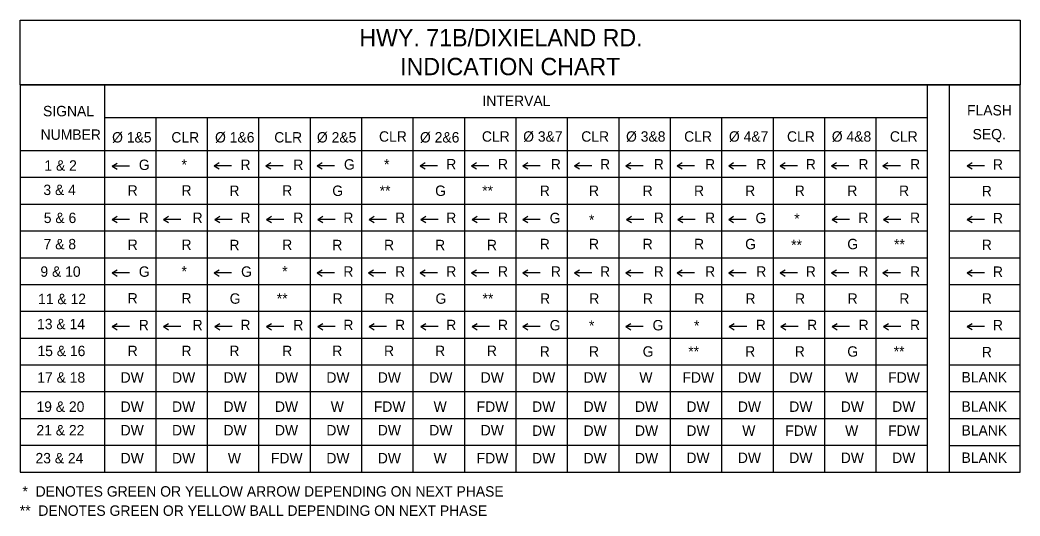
# Model space of a CAD drawing. Extents: x -19.5 to 29.5, y 0.4 to 10.6.
# Drawn here: x -12.11 to -4.42, y 0.78 to 4.6 of the extents above; entities that cross this region are included whole.
import ezdxf

# ---------------------------------------------------------------- set-up
doc = ezdxf.new("R2010")
doc.units = 0
for name, color, linetype in [('$', 7, 'Continuous'), ('PHASE', 7, 'Continuous'), ('TBLBDR', 7, 'Continuous'), ('TBLLINE', 7, 'Continuous'), ('TBLTEXT', 7, 'Continuous'), ('TITEXT', 7, 'Continuous')]:
    doc.layers.add(name, color=color, linetype=linetype)

msp = doc.modelspace()

# ---------------------------------------------------------------- linework, layer by layer
at = {"layer": 'PHASE'}
for p, q in [((-11.4033, 3.4746), (-11.3649, 3.4989)), ((-11.4033, 3.4746), (-11.3649, 3.4503)), ((-11.2697, 3.4746), (-11.4033, 3.4746)), ((-10.6165, 3.4775), (-10.5781, 3.5018)), ((-10.6165, 3.4775), (-10.5781, 3.4532)), ((-10.4829, 3.4775), (-10.6165, 3.4775)), ((-10.2207, 3.4775), (-10.1822, 3.5018)), ((-10.2207, 3.4775), (-10.1822, 3.4532)), ((-10.0871, 3.4775), (-10.2207, 3.4775)), ((-9.8249, 3.4775), (-9.7864, 3.5018)), ((-9.8249, 3.4775), (-9.7864, 3.4532)), ((-9.6912, 3.4775), (-9.8249, 3.4775)), ((-9.0332, 3.4783), (-8.9947, 3.5026)), ((-9.0332, 3.4783), (-8.9947, 3.454)), ((-8.8996, 3.4783), (-9.0332, 3.4783)), ((-8.6373, 3.4783), (-8.5989, 3.5026)), ((-8.6373, 3.4783), (-8.5989, 3.454)), ((-8.5037, 3.4783), (-8.6373, 3.4783)), ((-8.2415, 3.4783), (-8.203, 3.5026)), ((-8.2415, 3.4783), (-8.203, 3.454)), ((-8.1079, 3.4783), (-8.2415, 3.4783)), ((-7.8457, 3.4783), (-7.8072, 3.5026)), ((-7.8457, 3.4783), (-7.8072, 3.454)), ((-7.712, 3.4783), (-7.8457, 3.4783)), ((-7.4498, 3.4783), (-7.4114, 3.5026)), ((-7.4498, 3.4783), (-7.4114, 3.454)), ((-7.3162, 3.4783), (-7.4498, 3.4783)), ((-7.054, 3.4783), (-7.0155, 3.5026)), ((-7.054, 3.4783), (-7.0155, 3.454)), ((-6.9204, 3.4783), (-7.054, 3.4783)), ((-6.6581, 3.4783), (-6.6197, 3.5026)), ((-6.6581, 3.4783), (-6.6197, 3.454)), ((-6.5245, 3.4783), (-6.6581, 3.4783)), ((-6.2623, 3.4783), (-6.2238, 3.5026)), ((-6.2623, 3.4783), (-6.2238, 3.454)), ((-6.1287, 3.4783), (-6.2623, 3.4783)), ((-5.8665, 3.4783), (-5.828, 3.5026)), ((-5.8665, 3.4783), (-5.828, 3.454)), ((-5.7328, 3.4783), (-5.8665, 3.4783)), ((-5.4706, 3.4783), (-5.4322, 3.5026)), ((-5.4706, 3.4783), (-5.4322, 3.454)), ((-5.337, 3.4783), (-5.4706, 3.4783)), ((-4.8224, 3.4775), (-4.7839, 3.5018)), ((-4.8224, 3.4775), (-4.7839, 3.4532)), ((-4.6888, 3.4775), (-4.8224, 3.4775)), ((-11.4033, 3.0652), (-11.3649, 3.0895)), ((-11.0075, 3.0652), (-10.969, 3.0895)), ((-10.6117, 3.0652), (-10.5732, 3.0895)), ((-10.2158, 3.0652), (-10.1773, 3.0895)), ((-9.82, 3.0652), (-9.7815, 3.0895)), ((-9.4241, 3.0652), (-9.3857, 3.0895)), ((-9.0283, 3.0652), (-8.9898, 3.0895)), ((-8.6325, 3.0652), (-8.594, 3.0895)), ((-8.2415, 3.0652), (-8.203, 3.0895)), ((-7.4449, 3.0652), (-7.4065, 3.0895)), ((-7.0491, 3.0652), (-7.0106, 3.0895)), ((-6.6581, 3.0652), (-6.6197, 3.0895)), ((-5.8616, 3.0652), (-5.8231, 3.0895)), ((-5.4657, 3.0652), (-5.4273, 3.0895)), ((-4.8224, 3.0648), (-4.7839, 3.0891)), ((-11.4033, 3.0652), (-11.3649, 3.0409)), ((-11.2697, 3.0652), (-11.4033, 3.0652)), ((-11.0075, 3.0652), (-10.969, 3.0409)), ((-10.8739, 3.0652), (-11.0075, 3.0652)), ((-10.6117, 3.0652), (-10.5732, 3.0409)), ((-10.478, 3.0652), (-10.6117, 3.0652)), ((-10.2158, 3.0652), (-10.1773, 3.0409)), ((-10.0822, 3.0652), (-10.2158, 3.0652)), ((-9.82, 3.0652), (-9.7815, 3.0409)), ((-9.6864, 3.0652), (-9.82, 3.0652)), ((-9.4241, 3.0652), (-9.3857, 3.0409)), ((-9.2905, 3.0652), (-9.4241, 3.0652)), ((-9.0283, 3.0652), (-8.9898, 3.0409)), ((-8.8947, 3.0652), (-9.0283, 3.0652)), ((-8.6325, 3.0652), (-8.594, 3.0409)), ((-8.4988, 3.0652), (-8.6325, 3.0652)), ((-8.2415, 3.0652), (-8.203, 3.0409)), ((-8.1079, 3.0652), (-8.2415, 3.0652)), ((-7.4449, 3.0652), (-7.4065, 3.0409)), ((-7.3113, 3.0652), (-7.4449, 3.0652)), ((-7.0491, 3.0652), (-7.0106, 3.0409)), ((-6.9155, 3.0652), (-7.0491, 3.0652)), ((-6.6581, 3.0652), (-6.6197, 3.0409)), ((-6.5245, 3.0652), (-6.6581, 3.0652)), ((-5.8616, 3.0652), (-5.8231, 3.0409)), ((-5.728, 3.0652), (-5.8616, 3.0652)), ((-5.4657, 3.0652), (-5.4273, 3.0409)), ((-5.3321, 3.0652), (-5.4657, 3.0652)), ((-4.8224, 3.0648), (-4.7839, 3.0406)), ((-4.6888, 3.0648), (-4.8224, 3.0648)), ((-11.4033, 2.6529), (-11.3649, 2.6772)), ((-11.4033, 2.6529), (-11.3649, 2.6287)), ((-11.2697, 2.6529), (-11.4033, 2.6529)), ((-10.6165, 2.6529), (-10.5781, 2.6772)), ((-10.6165, 2.6529), (-10.5781, 2.6287)), ((-10.4829, 2.6529), (-10.6165, 2.6529)), ((-9.8249, 2.6529), (-9.7864, 2.6772)), ((-9.8249, 2.6529), (-9.7864, 2.6287)), ((-9.6912, 2.6529), (-9.8249, 2.6529)), ((-9.429, 2.6529), (-9.3905, 2.6772)), ((-9.429, 2.6529), (-9.3905, 2.6287)), ((-9.2954, 2.6529), (-9.429, 2.6529)), ((-9.0332, 2.6529), (-8.9947, 2.6772)), ((-9.0332, 2.6529), (-8.9947, 2.6287)), ((-8.8996, 2.6529), (-9.0332, 2.6529)), ((-8.6373, 2.6529), (-8.5989, 2.6772)), ((-8.6373, 2.6529), (-8.5989, 2.6287)), ((-8.5037, 2.6529), (-8.6373, 2.6529)), ((-8.2415, 2.6529), (-8.203, 2.6772)), ((-8.2415, 2.6529), (-8.203, 2.6287)), ((-8.1079, 2.6529), (-8.2415, 2.6529)), ((-7.8457, 2.6529), (-7.8072, 2.6772)), ((-7.8457, 2.6529), (-7.8072, 2.6287)), ((-7.712, 2.6529), (-7.8457, 2.6529)), ((-7.4498, 2.6529), (-7.4114, 2.6772)), ((-7.4498, 2.6529), (-7.4114, 2.6287)), ((-7.3162, 2.6529), (-7.4498, 2.6529)), ((-7.054, 2.6529), (-7.0155, 2.6772)), ((-7.054, 2.6529), (-7.0155, 2.6287)), ((-6.9204, 2.6529), (-7.054, 2.6529)), ((-6.6581, 2.6529), (-6.6197, 2.6772)), ((-6.6581, 2.6529), (-6.6197, 2.6287)), ((-6.5245, 2.6529), (-6.6581, 2.6529)), ((-6.2623, 2.6529), (-6.2238, 2.6772)), ((-6.2623, 2.6529), (-6.2238, 2.6287)), ((-6.1287, 2.6529), (-6.2623, 2.6529)), ((-5.8665, 2.6529), (-5.828, 2.6772)), ((-5.8665, 2.6529), (-5.828, 2.6287)), ((-5.7328, 2.6529), (-5.8665, 2.6529)), ((-5.4706, 2.6529), (-5.4322, 2.6772)), ((-5.4706, 2.6529), (-5.4322, 2.6287)), ((-5.337, 2.6529), (-5.4706, 2.6529)), ((-4.8224, 2.6529), (-4.7839, 2.6772)), ((-4.8224, 2.6529), (-4.7839, 2.6287)), ((-4.6888, 2.6529), (-4.8224, 2.6529)), ((-11.4033, 2.2407), (-11.3649, 2.2649)), ((-11.4033, 2.2407), (-11.3649, 2.2164)), ((-11.2697, 2.2407), (-11.4033, 2.2407)), ((-11.0075, 2.2407), (-10.969, 2.2649)), ((-11.0075, 2.2407), (-10.969, 2.2164)), ((-10.8739, 2.2407), (-11.0075, 2.2407)), ((-10.6117, 2.2407), (-10.5732, 2.2649)), ((-10.6117, 2.2407), (-10.5732, 2.2164)), ((-10.478, 2.2407), (-10.6117, 2.2407)), ((-10.2158, 2.2407), (-10.1773, 2.2649)), ((-10.2158, 2.2407), (-10.1773, 2.2164)), ((-10.0822, 2.2407), (-10.2158, 2.2407)), ((-9.82, 2.2407), (-9.7815, 2.2649)), ((-9.82, 2.2407), (-9.7815, 2.2164)), ((-9.6864, 2.2407), (-9.82, 2.2407)), ((-9.4241, 2.2407), (-9.3857, 2.2649)), ((-9.4241, 2.2407), (-9.3857, 2.2164)), ((-9.2905, 2.2407), (-9.4241, 2.2407)), ((-9.0283, 2.2407), (-8.9898, 2.2649)), ((-9.0283, 2.2407), (-8.9898, 2.2164)), ((-8.8947, 2.2407), (-9.0283, 2.2407)), ((-8.6325, 2.2407), (-8.594, 2.2649)), ((-8.6325, 2.2407), (-8.594, 2.2164)), ((-8.4988, 2.2407), (-8.6325, 2.2407)), ((-8.2415, 2.2407), (-8.203, 2.2649)), ((-8.2415, 2.2407), (-8.203, 2.2164)), ((-8.1079, 2.2407), (-8.2415, 2.2407)), ((-7.4498, 2.2407), (-7.4114, 2.2649)), ((-7.4498, 2.2407), (-7.4114, 2.2164)), ((-7.3162, 2.2407), (-7.4498, 2.2407)), ((-6.6533, 2.2407), (-6.6148, 2.2649)), ((-6.6533, 2.2407), (-6.6148, 2.2164)), ((-6.5196, 2.2407), (-6.6533, 2.2407)), ((-6.2574, 2.2407), (-6.219, 2.2649)), ((-6.2574, 2.2407), (-6.219, 2.2164)), ((-6.1238, 2.2407), (-6.2574, 2.2407)), ((-5.8616, 2.2407), (-5.8231, 2.2649)), ((-5.8616, 2.2407), (-5.8231, 2.2164)), ((-5.728, 2.2407), (-5.8616, 2.2407)), ((-5.4657, 2.2407), (-5.4273, 2.2649)), ((-5.4657, 2.2407), (-5.4273, 2.2164)), ((-5.3321, 2.2407), (-5.4657, 2.2407)), ((-4.8224, 2.2411), (-4.7839, 2.2653)), ((-4.8224, 2.2411), (-4.7839, 2.2168)), ((-4.6888, 2.2411), (-4.8224, 2.2411))]:
    msp.add_line(p, q, dxfattribs=at)
at = {"layer": 'TBLBDR'}
for p, q in [((-12.1107, 4.1013), (-12.1107, 1.1214)), ((-12.1107, 4.1013), (-4.4161, 4.1013)), ((-11.4602, 1.1214), (-11.4602, 4.1013)), ((-5.1267, 1.1214), (-5.1267, 4.1013)), ((-4.9604, 4.1013), (-4.9604, 1.1214)), ((-4.4161, 1.1214), (-4.4161, 4.1013)), ((-8.2934, 1.1214), (-8.2934, 3.8486)), ((-12.1107, 3.5951), (-5.1267, 3.5951)), ((-4.9604, 3.5951), (-4.4161, 3.5951)), ((-12.1107, 1.9459), (-5.1267, 1.9459)), ((-4.9604, 1.9452), (-4.4161, 1.9452)), ((-12.1107, 1.1214), (-4.4161, 1.1214))]:
    msp.add_line(p, q, dxfattribs=at)
msp.add_lwpolyline([(-12.1107, 4.599), (-4.4161, 4.599), (-4.4161, 4.1013), (-12.1107, 4.1013)], close=True, dxfattribs=at)
at = {"layer": 'TBLLINE'}
for p, q in [((-11.4602, 3.8486), (-5.1267, 3.8486)), ((-11.0643, 1.1214), (-11.0643, 3.8486)), ((-10.6685, 1.1214), (-10.6685, 3.8486)), ((-10.2726, 1.1214), (-10.2726, 3.8486)), ((-9.8768, 1.1214), (-9.8768, 3.8486)), ((-9.481, 1.1214), (-9.481, 3.8486)), ((-9.0851, 1.1214), (-9.0851, 3.8486)), ((-8.6893, 1.1214), (-8.6893, 3.8486)), ((-7.8976, 1.1214), (-7.8976, 3.8486)), ((-7.5018, 1.1214), (-7.5018, 3.8486)), ((-7.1059, 1.1214), (-7.1059, 3.8486)), ((-6.7101, 1.1214), (-6.7101, 3.8486)), ((-6.3143, 1.1214), (-6.3143, 3.8486)), ((-5.9184, 1.1214), (-5.9184, 3.8486)), ((-5.5226, 1.1214), (-5.5226, 3.8486)), ((-12.1107, 3.3889), (-5.1267, 3.3889)), ((-4.9604, 3.3897), (-4.4161, 3.3897)), ((-12.1107, 3.1828), (-5.1267, 3.1828)), ((-4.9604, 3.1832), (-4.4161, 3.1832)), ((-12.1107, 2.9766), (-5.1267, 2.9766)), ((-4.9604, 2.9766), (-4.4161, 2.9766)), ((-12.1107, 2.7705), (-5.1267, 2.7705)), ((-4.9604, 2.7701), (-4.4161, 2.7701)), ((-12.1107, 2.5644), (-5.1267, 2.5644)), ((-4.9604, 2.5648), (-4.4161, 2.5648)), ((-12.1107, 2.3582), (-5.1267, 2.3582)), ((-4.9604, 2.3582), (-4.4161, 2.3582)), ((-12.1107, 2.1521), (-5.1267, 2.1521)), ((-4.9604, 2.1517), (-4.4161, 2.1517)), ((-12.1107, 1.7398), (-5.1267, 1.7398)), ((-4.9604, 1.7398), (-4.4161, 1.7398)), ((-12.1107, 1.5337), (-5.1267, 1.5337)), ((-4.9604, 1.5333), (-4.4161, 1.5333)), ((-12.1107, 1.3275), (-5.1267, 1.3275)), ((-4.9604, 1.3267), (-4.4161, 1.3267))]:
    msp.add_line(p, q, dxfattribs=at)

# ---------------------------------------------------------------- texts
at = {"layer": '$'}
for s, p in [('HWY. 71B/DIXIELAND RD.', (-9.5004, 4.3964)), ('INDICATION CHART', (-9.1861, 4.1744))]:
    msp.add_text(s, height=0.133334, dxfattribs=at).set_placement(p)
at = {"layer": 'TBLTEXT'}
for s, height, p in [('1 & 2', 0.08, (-11.9241, 3.4401)), ('G', 0.08, (-11.1973, 3.4451)), ('*', 0.08, (-10.8689, 3.4467)), ('R', 0.08, (-10.415, 3.4456)), ('R', 0.08, (-10.0086, 3.4451)), ('G', 0.08, (-9.6188, 3.448)), ('*', 0.08, (-9.3102, 3.4488)), ('R', 0.08, (-8.8316, 3.4497)), ('R', 0.08, (-8.4332, 3.4497)), ('R', 0.08, (-8.0263, 3.4493)), ('R', 0.08, (-7.6477, 3.4493)), ('R', 0.08, (-7.2346, 3.4493)), ('R', 0.08, (-6.8393, 3.4493)), ('R', 0.08, (-6.4457, 3.4493)), ('R', 0.08, (-6.0644, 3.4493)), ('R', 0.08, (-5.6596, 3.4493)), ('R', 0.08, (-5.2615, 3.4493)), ('R', 0.08, (-4.6245, 3.4476)), ('3 & 4', 0.08, (-11.9317, 3.2525)), ('R', 0.08, (-11.2831, 3.2475)), ('R', 0.08, (-10.8689, 3.2475)), ('R', 0.08, (-10.5003, 3.2455)), ('R', 0.08, (-10.094, 3.2475)), ('G', 0.08, (-9.7087, 3.2455)), ('**', 0.08, (-9.3439, 3.2455)), ('G', 0.08, (-8.917, 3.2455)), ('**', 0.08, (-8.5547, 3.2455)), ('R', 0.08, (-8.1116, 3.2455)), ('R', 0.08, (-7.7331, 3.2455)), ('R', 0.08, (-7.3199, 3.2455)), ('R', 0.08, (-6.9247, 3.2455)), ('R', 0.08, (-6.5311, 3.2455)), ('R', 0.08, (-6.1497, 3.2455)), ('R', 0.08, (-5.745, 3.2455)), ('R', 0.08, (-5.3469, 3.2455)), ('R', 0.08, (-4.7099, 3.2423)), ('5 & 6', 0.08, (-11.9287, 3.037)), ('R', 0.08, (-11.1977, 3.037)), ('R', 0.08, (-10.7836, 3.037)), ('R', 0.08, (-10.415, 3.0375)), ('R', 0.08, (-10.0086, 3.037)), ('R', 0.08, (-9.6233, 3.0375)), ('R', 0.08, (-9.2249, 3.0375)), ('R', 0.08, (-8.8316, 3.0375)), ('R', 0.08, (-8.4332, 3.0375)), ('G', 0.08, (-8.0354, 3.0357)), ('*', 0.08, (-7.7331, 3.0217)), ('R', 0.08, (-7.2346, 3.0375)), ('R', 0.08, (-6.8393, 3.0375)), ('G', 0.08, (-6.4521, 3.0357)), ('*', 0.08, (-6.1533, 3.0309)), ('R', 0.08, (-5.6603, 3.0375)), ('R', 0.08, (-5.2622, 3.0375)), ('R', 0.08, (-4.6245, 3.0349)), ('7 & 8', 0.08, (-11.9302, 2.8351)), ('R', 0.08, (-11.2831, 2.8301)), ('R', 0.08, (-10.8689, 2.8301)), ('R', 0.08, (-10.5003, 2.8281)), ('R', 0.08, (-10.094, 2.8301)), ('R', 0.08, (-9.7087, 2.8281)), ('R', 0.08, (-9.3102, 2.8281)), ('R', 0.08, (-8.917, 2.8281)), ('R', 0.08, (-8.5186, 2.8281)), ('R', 0.08, (-8.1116, 2.8356)), ('R', 0.08, (-7.7331, 2.8356)), ('R', 0.08, (-7.3199, 2.8356)), ('R', 0.08, (-6.9247, 2.8356)), ('G', 0.08, (-6.5311, 2.8356)), ('**', 0.08, (-6.1772, 2.8281)), ('G', 0.08, (-5.745, 2.8356)), ('**', 0.08, (-5.3855, 2.8331)), ('R', 0.08, (-4.7099, 2.8292)), ('9 & 10', 0.08, (-11.9546, 2.6238)), ('G', 0.08, (-11.1973, 2.6234)), ('*', 0.08, (-10.8689, 2.6254)), ('G', 0.08, (-10.4105, 2.6234)), ('*', 0.08, (-10.094, 2.6254)), ('R', 0.08, (-9.6233, 2.624)), ('R', 0.08, (-9.2249, 2.624)), ('R', 0.08, (-8.8316, 2.6244)), ('R', 0.08, (-8.4332, 2.6244)), ('R', 0.08, (-8.0263, 2.624)), ('R', 0.08, (-7.6477, 2.624)), ('R', 0.08, (-7.2346, 2.624)), ('R', 0.08, (-6.8393, 2.624)), ('R', 0.08, (-6.4457, 2.624)), ('R', 0.08, (-6.0644, 2.624)), ('R', 0.08, (-5.6596, 2.624)), ('R', 0.08, (-5.2615, 2.624)), ('R', 0.08, (-4.6245, 2.623)), ('11 & 12', 0.08, (-11.9729, 2.4132)), ('R', 0.08, (-11.2831, 2.4182)), ('R', 0.08, (-10.8689, 2.4182)), ('G', 0.08, (-10.4979, 2.4162)), ('**', 0.08, (-10.1356, 2.4162)), ('R', 0.08, (-9.7062, 2.4162)), ('R', 0.08, (-9.3078, 2.4162)), ('G', 0.08, (-8.9145, 2.4162)), ('**', 0.08, (-8.5523, 2.4162)), ('R', 0.08, (-8.1092, 2.4162)), ('R', 0.08, (-7.7307, 2.4162)), ('R', 0.08, (-7.3175, 2.4162)), ('R', 0.08, (-6.9222, 2.4162)), ('R', 0.08, (-6.5286, 2.4162)), ('R', 0.08, (-6.1473, 2.4162)), ('R', 0.08, (-5.7425, 2.4162)), ('R', 0.08, (-5.3445, 2.4162)), ('R', 0.08, (-4.7099, 2.4173)), ('13 & 14', 0.08, (-11.9805, 2.2201)), ('R', 0.08, (-11.1977, 2.2124)), ('R', 0.08, (-10.7836, 2.2124)), ('R', 0.08, (-10.415, 2.213)), ('R', 0.08, (-10.0086, 2.2124)), ('R', 0.08, (-9.6233, 2.213)), ('R', 0.08, (-9.2249, 2.213)), ('R', 0.08, (-8.8316, 2.213)), ('R', 0.08, (-8.4332, 2.213)), ('G', 0.08, (-8.0354, 2.2112)), ('*', 0.08, (-7.7331, 2.2082)), ('G', 0.08, (-7.2437, 2.2112)), ('*', 0.08, (-6.9247, 2.2082)), ('R', 0.08, (-6.4497, 2.213)), ('R', 0.08, (-6.0539, 2.213)), ('R', 0.08, (-5.658, 2.213)), ('R', 0.08, (-5.2622, 2.213)), ('R', 0.08, (-4.6245, 2.2112)), ('15 & 16', 0.08, (-11.9774, 2.0133)), ('R', 0.08, (-11.2831, 2.0133)), ('R', 0.08, (-10.8689, 2.0133)), ('R', 0.08, (-10.5003, 2.0138)), ('R', 0.08, (-10.094, 2.0133)), ('R', 0.08, (-9.7087, 2.0138)), ('R', 0.08, (-9.3102, 2.0138)), ('R', 0.08, (-8.917, 2.0138)), ('R', 0.08, (-8.5186, 2.0138)), ('R', 0.08, (-8.1116, 2.0089)), ('R', 0.08, (-7.7331, 2.0089)), ('G', 0.08, (-7.3199, 2.0089)), ('**', 0.08, (-6.9689, 2.0089)), ('R', 0.08, (-6.5311, 2.0089)), ('R', 0.08, (-6.1497, 2.0089)), ('G', 0.08, (-5.745, 2.0089)), ('**', 0.08, (-5.388, 2.0089)), ('R', 0.08, (-4.7099, 2.0042)), ('17 & 18', 0.08, (-11.979, 1.8091)), ('DW', 0.08, (-11.3374, 1.8091)), ('DW', 0.08, (-10.9416, 1.8091)), ('DW', 0.08, (-10.5457, 1.8091)), ('DW', 0.08, (-10.1499, 1.8091)), ('DW', 0.08, (-9.754, 1.8091)), ('DW', 0.08, (-9.3582, 1.8091)), ('DW', 0.08, (-8.9624, 1.8091)), ('DW', 0.08, (-8.5665, 1.8091)), ('DW', 0.08, (-8.1707, 1.8091)), ('DW', 0.08, (-7.7748, 1.8091)), ('W', 0.08, (-7.3454, 1.8091)), ('FDW', 0.08, (-7.0139, 1.8091)), ('DW', 0.08, (-6.5873, 1.8091)), ('DW', 0.08, (-6.1915, 1.8091)), ('W', 0.08, (-5.762, 1.8091)), ('FDW', 0.08, (-5.4306, 1.8091)), ('BLANK', 0.08, (-4.8662, 1.8107)), ('19 & 20', 0.08, (-11.9851, 1.5846)), ('DW', 0.08, (-11.3374, 1.5846)), ('DW', 0.08, (-10.9416, 1.5846)), ('DW', 0.08, (-10.5457, 1.5846)), ('DW', 0.08, (-10.1499, 1.5846)), ('W', 0.08, (-9.7204, 1.5846)), ('FDW', 0.08, (-9.389, 1.5846)), ('W', 0.08, (-8.9288, 1.5846)), ('FDW', 0.08, (-8.5973, 1.5846)), ('DW', 0.08, (-8.1707, 1.5846)), ('DW', 0.08, (-7.7748, 1.5846)), ('DW', 0.08, (-7.379, 1.5846)), ('DW', 0.08, (-6.9832, 1.5846)), ('DW', 0.08, (-6.5873, 1.5846)), ('DW', 0.08, (-6.1915, 1.5846)), ('DW', 0.08, (-5.7956, 1.5846)), ('DW', 0.08, (-5.3998, 1.5846)), ('BLANK', 0.08, (-4.8662, 1.5858)), ('21 & 22', 0.08, (-11.9851, 1.4033)), ('DW', 0.08, (-11.3374, 1.4033)), ('DW', 0.08, (-10.9416, 1.4033)), ('DW', 0.08, (-10.5457, 1.4033)), ('DW', 0.08, (-10.1499, 1.4033)), ('DW', 0.08, (-9.754, 1.4033)), ('DW', 0.08, (-9.3582, 1.4033)), ('DW', 0.08, (-8.9624, 1.4033)), ('DW', 0.08, (-8.5665, 1.4033)), ('DW', 0.08, (-8.1707, 1.4)), ('DW', 0.08, (-7.7748, 1.4)), ('DW', 0.08, (-7.379, 1.4)), ('DW', 0.08, (-6.9832, 1.4)), ('W', 0.08, (-6.5537, 1.4)), ('FDW', 0.08, (-6.2223, 1.4)), ('W', 0.08, (-5.762, 1.4)), ('FDW', 0.08, (-5.4306, 1.4)), ('BLANK', 0.08, (-4.8662, 1.402)), ('23 & 24', 0.08, (-11.9927, 1.1884)), ('DW', 0.08, (-11.3374, 1.1884)), ('DW', 0.08, (-10.9416, 1.1884)), ('W', 0.08, (-10.5121, 1.1884)), ('FDW', 0.08, (-10.1807, 1.1884)), ('DW', 0.08, (-9.754, 1.1884)), ('DW', 0.08, (-9.3582, 1.1884)), ('W', 0.08, (-8.9288, 1.1884)), ('FDW', 0.08, (-8.5973, 1.1884)), ('DW', 0.08, (-8.1707, 1.1884)), ('DW', 0.08, (-7.7748, 1.1884)), ('DW', 0.08, (-7.379, 1.1884)), ('DW', 0.08, (-6.9832, 1.1911)), ('DW', 0.08, (-6.5873, 1.1911)), ('DW', 0.08, (-6.1915, 1.1911)), ('DW', 0.08, (-5.7956, 1.1911)), ('DW', 0.08, (-5.3998, 1.1911)), ('BLANK', 0.08, (-4.8662, 1.1919)), ('  *  DENOTES GREEN OR YELLOW ARROW DEPENDING ON NEXT PHASE', 0.080131, (-12.1525, 0.9324)), (' **  DENOTES GREEN OR YELLOW BALL DEPENDING ON NEXT PHASE', 0.080131, (-12.1433, 0.7845))]:
    msp.add_text(s, height=height, dxfattribs=at).set_placement(p)
at = {"layer": 'TITEXT'}
for s, p in [('INTERVAL', (-8.5531, 3.9372)), ('SIGNAL', (-11.9347, 3.8585)), ('FLASH', (-4.8237, 3.8648)), ('NUMBER', (-11.9529, 3.6772)), ('%%C 1&5', (-11.4029, 3.6566)), ('CLR', (-10.9467, 3.6566)), ('%%C 1&6', (-10.6107, 3.6566)), ('CLR', (-10.155, 3.6566)), ('%%C 2&5', (-9.8266, 3.6566)), ('CLR', (-9.3489, 3.663)), ('%%C 2&6', (-9.0334, 3.6566)), ('CLR', (-8.5572, 3.663)), ('%%C 3&7', (-8.2395, 3.663)), ('CLR', (-7.7925, 3.663)), ('%%C 3&8', (-7.4478, 3.663)), ('CLR', (-7.0008, 3.663)), ('%%C 4&7', (-6.6561, 3.663)), ('CLR', (-6.2091, 3.663)), ('%%C 4&8', (-5.8644, 3.663)), ('CLR', (-5.4174, 3.663)), ('SEQ.', (-4.781, 3.6807))]:
    msp.add_text(s, height=0.08, dxfattribs=at).set_placement(p)

doc.saveas('drawing.dxf')
